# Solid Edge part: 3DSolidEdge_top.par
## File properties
Author: Administrator
Last saved by: Administrator
Revision: 48
Accuracy: 0.990
Agile_Description: Top Part (for arrow control pad)
Modeled_By: L. Conard
Part_Number: ITEM-SE-00002
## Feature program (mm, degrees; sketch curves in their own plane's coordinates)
body "unnamed Body 1"
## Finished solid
Body 1: solid body, 136 faces, 326 edges, 190 vertices.
  Faces by surface: cylinder 65, plane 54, torus 13, sphere 4
  Edges by curve: line 207, circle 85, ellipse 24, spline 6, curve on surface 4
Bounding box of the edges (mm; curved faces can reach further): 64.000 x 105.000 x 11.500, from (0, 0, -9.5) to (64, 105, 2).
Cylindrical faces by radius (mm): R0.25 x28, R0.75 x3, R1 x6, R2.5 x10, R2.54 x4, R2.75 x4, R4 x8, R5 x2
Toroidal faces (ring radius, tube radius in mm): R0.04 r2.5 x4, R1.25 r0.25 x4, R5 r2.5 x3, R5.25 r0.25 x2
Spherical faces by radius (mm): R4 x4
Planar faces by outward normal: +x 10, +y 8, +z 7, -x 10, -y 10, -z 1, oblique 8
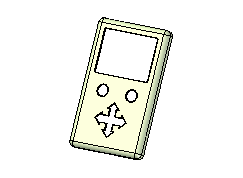
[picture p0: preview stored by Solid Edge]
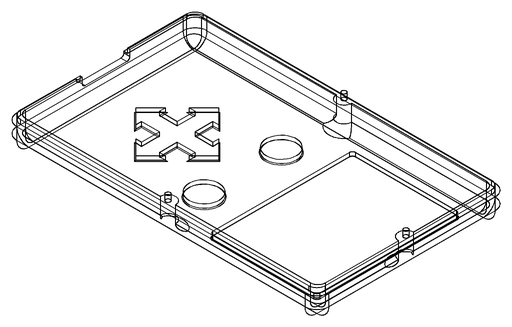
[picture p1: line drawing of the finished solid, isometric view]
